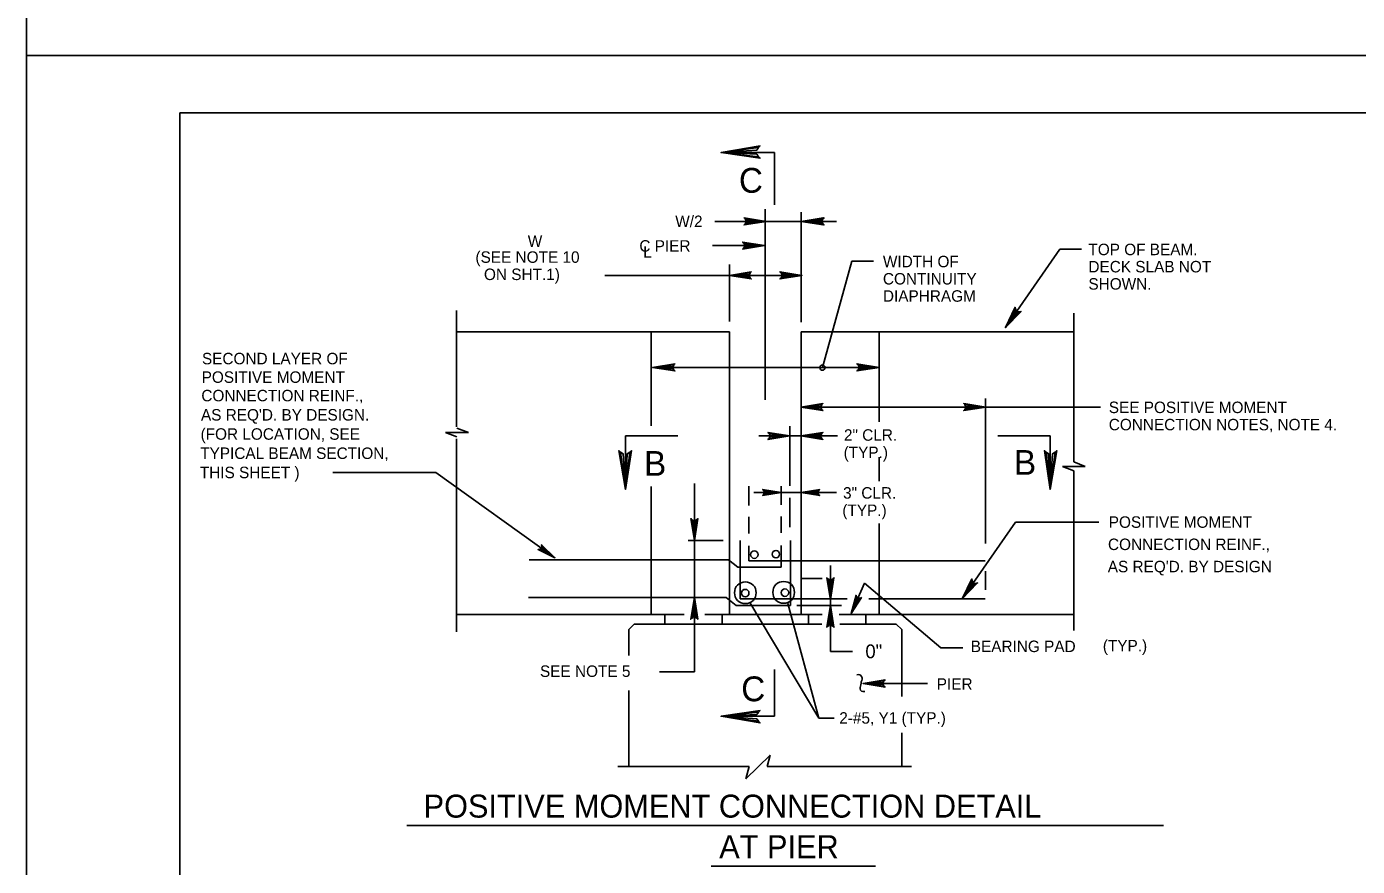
# Model space of a CAD drawing. Extents: x 641517 to 642372, y 298537 to 300319.
# Drawn here: x 641517 to 641864.7, y 299512.8 to 299732.1 of the extents above; entities that cross this region are included whole.
import ezdxf

# ---------------------------------------------------------------- set-up
doc = ezdxf.new("R2010")
doc.units = 0
for name, color, linetype in [('1', 7, 'Continuous'), ('2', 7, 'Continuous'), ('3', 7, 'Continuous'), ('PLT-BNDY', 7, 'Continuous')]:
    doc.layers.add(name, color=color, linetype=linetype)

msp = doc.modelspace()

# ---------------------------------------------------------------- linework, layer by layer
at = {"layer": '1'}
for p, q in [((641709.99, 299634.69), (641709.99, 299684.42)), ((641680.22, 299627.84), (641680.22, 299652.44)), ((641700.62, 299578.61), (641700.62, 299652.44)), ((641719.37, 299578.61), (641719.37, 299652.44)), ((641739.76, 299628.96), (641739.76, 299652.44)), ((641739.76, 299613.39), (641739.76, 299619.71)), ((641680.22, 299578.61), (641680.22, 299612.04)), ((641739.76, 299578.61), (641739.76, 299602.33)), ((641702.81, 299590.97), (641700.38, 299592.86)), ((641702.38, 299580.97), (641699.8, 299583.08))]:
    msp.add_line(p, q, dxfattribs=at)
msp.add_spline([(641733.93, 299562.89), (641734.71, 299562.83), (641735.12, 299562.43), (641735.29, 299561.7), (641735.08, 299561.01), (641734.94, 299560.28), (641734.81, 299559.55), (641734.89, 299558.82), (641735.44, 299558.51), (641736.02, 299558.51)], degree=3, dxfattribs=at)
at = {"layer": '2'}
for p, q in [((641557.05, 299145.62), (641557.05, 299709.62)), ((641557.05, 299709.62), (642343.05, 299709.62)), ((641712.41, 299699.24), (641698.46, 299699.24)), ((641712.41, 299685.61), (641712.41, 299699.24)), ((641719.37, 299654.93), (641719.37, 299683.68)), ((641710.18, 299681.26), (641696.8, 299681.26)), ((641719.42, 299681.26), (641710.18, 299681.26)), ((641728.61, 299681.26), (641719.37, 299681.26)), ((641709.79, 299674.94), (641696.21, 299674.94)), ((641792.61, 299674.03), (641786.93, 299674.03)), ((641700.62, 299655.13), (641700.62, 299670.02)), ((641732.64, 299670.88), (641724.92, 299643.07)), ((641738.22, 299670.88), (641732.64, 299670.88)), ((641700.62, 299667.16), (641668.08, 299667.16)), ((641719.56, 299667.16), (641700.62, 299667.16)), ((641629.36, 299627.61), (641629.36, 299658.02)), ((641790.62, 299618.46), (641790.62, 299657.28)), ((641629.36, 299652.44), (641700.62, 299652.44)), ((641719.37, 299652.44), (641790.62, 299652.44)), ((641739.76, 299643.14), (641680.57, 299643.14)), ((641797.52, 299632.75), (641719.37, 299632.75)), ((641629.41, 299627.29), (641632.43, 299626.11)), ((641716.37, 299612.2), (641716.37, 299627.78)), ((641632.43, 299626.11), (641626.49, 299626.11)), ((641626.49, 299626.11), (641629.41, 299624.97)), ((641629.36, 299574.06), (641629.36, 299624.45)), ((641687.14, 299625.23), (641673.51, 299625.23)), ((641673.51, 299625.23), (641673.51, 299611.28)), ((641728.84, 299625.24), (641708.31, 299625.24)), ((641770.77, 299625.23), (641784.4, 299625.23)), ((641784.4, 299625.23), (641784.4, 299611.28)), ((641793.58, 299617.28), (641787.65, 299617.28)), ((641787.65, 299617.28), (641790.57, 299616.14)), ((641790.57, 299618.46), (641793.58, 299617.28)), ((641790.62, 299574.4), (641790.62, 299616.14)), ((641597.02, 299615.67), (641623.96, 299615.67)), ((641623.96, 299615.67), (641655.06, 299593.42)), ((641691.46, 299597.93), (641691.46, 299612.78)), ((641705.69, 299607.03), (641705.69, 299612.15)), ((641714.15, 299610.46), (641706.96, 299610.46)), ((641714.15, 299607.24), (641714.15, 299612.15)), ((641719.37, 299610.46), (641714.15, 299610.46)), ((641716.37, 299601.42), (641716.37, 299609.05)), ((641728.58, 299610.46), (641719.37, 299610.46)), ((641705.69, 299599.75), (641705.69, 299604.12)), ((641714.15, 299599.95), (641714.15, 299604.22)), ((641797.12, 299602.72), (641775.34, 299602.72)), ((641698.96, 299597.93), (641689.85, 299597.93)), ((641691.46, 299583.08), (641691.46, 299597.93)), ((641703.43, 299582.66), (641703.43, 299597.93)), ((641705.69, 299592.66), (641705.69, 299596.52)), ((641714.15, 299590.97), (641714.15, 299596.62)), ((641716.55, 299580.97), (641716.55, 299597.93)), ((641648.35, 299592.86), (641700.38, 299592.86)), ((641705.69, 299592.66), (641767.44, 299592.66)), ((641702.81, 299590.97), (641714.15, 299590.97)), ((641719.37, 299587.99), (641724.86, 299587.99)), ((641755.88, 299569.86), (641735.94, 299586.82)), ((641648.12, 299583.08), (641699.8, 299583.08)), ((641691.46, 299563.65), (641691.46, 299583.08)), ((641703.43, 299582.66), (641731.4, 299582.66)), ((641737.04, 299582.66), (641767.44, 299582.66)), ((641629.36, 299578.61), (641688.77, 299578.61)), ((641683.74, 299576.08), (641683.74, 299578.61)), ((641694.17, 299578.61), (641719.37, 299578.61)), ((641698.74, 299576.08), (641698.74, 299578.61)), ((641702.38, 299580.97), (641716.55, 299580.97)), ((641729.93, 299580.97), (641718.21, 299580.97)), ((641719.37, 299578.61), (641724.86, 299578.61)), ((641721.24, 299576.08), (641721.24, 299578.61)), ((641729.26, 299578.61), (641790.62, 299578.61)), ((641736.24, 299576.08), (641736.24, 299578.61)), ((641674.36, 299574.67), (641675.77, 299576.08)), ((641674.36, 299567.9), (641674.36, 299574.67)), ((641675.77, 299576.08), (641724.75, 299576.08)), ((641729.48, 299576.08), (641744.21, 299576.08)), ((641745.62, 299574.67), (641744.21, 299576.08)), ((641745.62, 299557.2), (641745.62, 299574.67)), ((641761.62, 299569.86), (641755.88, 299569.86)), ((641712.41, 299564.25), (641712.41, 299552.02)), ((641691.46, 299563.65), (641682.36, 299563.65)), ((641752.34, 299560.59), (641735.55, 299560.59)), ((641674.36, 299538.8), (641674.36, 299558.75)), ((641712.41, 299552.02), (641698.46, 299552.02)), ((641727.99, 299551.57), (641723.96, 299551.57)), ((641745.62, 299538.94), (641745.62, 299547.72)), ((641704.94, 299535.71), (641711.3, 299541.85)), ((641711.3, 299541.85), (641710.47, 299538.93)), ((641705.8, 299538.93), (641671.44, 299538.93)), ((641704.91, 299535.71), (641705.77, 299538.93)), ((641748.16, 299538.93), (641710.47, 299538.93)), ((641616.38, 299523.5), (641814.01, 299523.5)), ((641695.83, 299512.92), (641738.77, 299512.92))]:
    msp.add_line(p, q, dxfattribs=at)
for points in [[(641708.18, 299700.53), (641707.75, 299699.89), (641698.46, 299699.24), (641708.18, 299700.53), (641708.62, 299700.97), (641698.46, 299699.24), (641707.75, 299698.81), (641708.18, 299698.16), (641698.46, 299699.24), (641708.62, 299697.73), (641708.18, 299698.16)], [(641776.43, 299657.67), (641775.99, 299657.73), (641772.71, 299653.52), (641776.43, 299657.67), (641776.8, 299657.77), (641772.71, 299653.52), (641775.53, 299658.05), (641775.31, 299658.43), (641772.71, 299653.52), (641775.26, 299658.83), (641775.31, 299658.43)], [(641686.11, 299642.44), (641685.9, 299642.84), (641680.57, 299643.14), (641686.11, 299642.44), (641686.39, 299642.2), (641680.57, 299643.14), (641685.9, 299643.4), (641686.09, 299643.8), (641680.57, 299643.14), (641686.39, 299644.06), (641686.09, 299643.8)], [(641734.23, 299643.83), (641734.43, 299643.43), (641739.76, 299643.14), (641734.23, 299643.83), (641733.94, 299644.07), (641739.76, 299643.14), (641734.44, 299642.87), (641734.24, 299642.48), (641739.76, 299643.14), (641733.94, 299642.21), (641734.24, 299642.48)], [(641672.21, 299621), (641672.86, 299620.57), (641673.51, 299611.28), (641672.21, 299621), (641671.78, 299621.43), (641673.51, 299611.28), (641673.94, 299620.57), (641674.59, 299621), (641673.51, 299611.28), (641675.02, 299621.43), (641674.59, 299621)], [(641785.7, 299621), (641785.05, 299620.57), (641784.4, 299611.28), (641785.7, 299621), (641786.13, 299621.43), (641784.4, 299611.28), (641783.97, 299620.57), (641783.32, 299621), (641784.4, 299611.28), (641782.89, 299621.43), (641783.32, 299621)], [(641709.53, 299611.04), (641709.7, 299610.71), (641714.15, 299610.46), (641709.53, 299611.04), (641709.3, 299611.24), (641714.15, 299610.46), (641709.71, 299610.24), (641709.55, 299609.91), (641714.15, 299610.46), (641709.3, 299609.69), (641709.55, 299609.91)], [(641723.98, 299609.88), (641723.81, 299610.22), (641719.37, 299610.46), (641723.98, 299609.88), (641724.22, 299609.68), (641719.37, 299610.46), (641723.8, 299610.68), (641723.97, 299611.01), (641719.37, 299610.46), (641724.22, 299611.23), (641723.97, 299611.01)], [(641651.6, 299596.52), (641651.55, 299596.14), (641655.06, 299593.42), (641651.6, 299596.52), (641651.52, 299596.82), (641655.06, 299593.42), (641651.29, 299595.76), (641650.97, 299595.58), (641655.06, 299593.42), (641650.64, 299595.54), (641650.97, 299595.58)], [(641734.84, 299582.88), (641734.47, 299582.85), (641732.46, 299578.89), (641734.84, 299582.88), (641735.12, 299583.01), (641732.46, 299578.89), (641734.04, 299583.04), (641733.8, 299583.32), (641732.46, 299578.89), (641733.7, 299583.64), (641733.8, 299583.32)], [(641708.18, 299550.72), (641707.75, 299551.37), (641698.46, 299552.02), (641708.18, 299550.72), (641708.62, 299550.29), (641698.46, 299552.02), (641707.75, 299552.45), (641708.18, 299553.1), (641698.46, 299552.02), (641708.62, 299553.53), (641708.18, 299553.1)]]:
    msp.add_lwpolyline(points, dxfattribs=at)
for centre, radius in [((641724.92, 299643.07), 0.679), ((641707.13, 299594.24), 0.977), ((641712.76, 299594.35), 0.977), ((641704.78, 299584.3), 2.84), ((641704.76, 299584.19), 0.977), ((641714.79, 299584.39), 2.84), ((641715.13, 299584.31), 0.977)]:
    msp.add_circle(centre, radius, dxfattribs=at)
at = {"layer": '3'}
for p, q in [((641772.71, 299653.52), (641786.93, 299674.03)), ((641642.2, 299652.44), (641642.2, 299652.44)), ((641767.5, 299597.14), (641767.5, 299635)), ((641761.43, 299582.66), (641775.34, 299602.72)), ((641727.01, 299591.38), (641727.01, 299582.66)), ((641767.5, 299585.05), (641767.5, 299589.95)), ((641735.94, 299586.82), (641732.46, 299578.89)), ((641723.96, 299551.57), (641705.94, 299581.71)), ((641723.96, 299551.57), (641715.84, 299581.46)), ((641727.01, 299582.66), (641727.01, 299580.98)), ((641727.01, 299582.49), (641727.01, 299582.49)), ((641727.01, 299580.98), (641727.01, 299580.98)), ((641727.01, 299580.98), (641727.01, 299568.97)), ((641727.01, 299568.97), (641732.78, 299568.97))]:
    msp.add_line(p, q, dxfattribs=at)
for points in [[(641704.73, 299681.95), (641704.94, 299681.55), (641710.18, 299681.26), (641704.73, 299681.95), (641704.46, 299682.19), (641710.18, 299681.26), (641704.94, 299681), (641704.75, 299680.61), (641710.18, 299681.26), (641704.46, 299680.35), (641704.75, 299680.61)], [(641704.73, 299681.95), (641704.94, 299681.55), (641710.18, 299681.26), (641704.73, 299681.95), (641704.46, 299682.19), (641710.18, 299681.26), (641704.94, 299681), (641704.75, 299680.61), (641710.18, 299681.26), (641704.46, 299680.35), (641704.75, 299680.61)], [(641724.82, 299680.58), (641724.61, 299680.97), (641719.37, 299681.26), (641724.82, 299680.58), (641725.09, 299680.34), (641719.37, 299681.26), (641724.61, 299681.52), (641724.8, 299681.91), (641719.37, 299681.26), (641725.09, 299682.17), (641724.8, 299681.91)], [(641725.08, 299680.58), (641724.87, 299680.97), (641719.63, 299681.26), (641725.08, 299680.58), (641725.35, 299680.34), (641719.63, 299681.26), (641724.87, 299681.52), (641725.06, 299681.91), (641719.63, 299681.26), (641725.35, 299682.17), (641725.06, 299681.91)], [(641704.34, 299674.26), (641704.55, 299674.65), (641709.79, 299674.94), (641704.34, 299674.26), (641704.06, 299674.02), (641709.79, 299674.94), (641704.55, 299675.2), (641704.36, 299675.59), (641709.79, 299674.94), (641704.06, 299675.85), (641704.36, 299675.59)], [(641706.07, 299666.48), (641705.86, 299666.87), (641700.62, 299667.16), (641706.07, 299666.48), (641706.34, 299666.24), (641700.62, 299667.16), (641705.86, 299667.42), (641706.05, 299667.81), (641700.62, 299667.16), (641706.34, 299668.07), (641706.05, 299667.81)], [(641714.11, 299667.85), (641714.31, 299667.45), (641719.56, 299667.16), (641714.11, 299667.85), (641713.83, 299668.09), (641719.56, 299667.16), (641714.31, 299666.9), (641714.12, 299666.51), (641719.56, 299667.16), (641713.83, 299666.25), (641714.12, 299666.51)], [(641724.77, 299632.08), (641724.56, 299632.48), (641719.32, 299632.77), (641724.77, 299632.08), (641725.04, 299631.85), (641719.32, 299632.77), (641724.56, 299633.03), (641724.75, 299633.42), (641719.32, 299632.77), (641725.04, 299633.68), (641724.75, 299633.42)], [(641762.12, 299633.43), (641762.32, 299633.04), (641767.57, 299632.75), (641762.12, 299633.43), (641761.84, 299633.67), (641767.57, 299632.75), (641762.32, 299632.49), (641762.13, 299632.1), (641767.57, 299632.75), (641761.84, 299631.84), (641762.13, 299632.1)], [(641710.97, 299625.93), (641711.17, 299625.53), (641716.42, 299625.24), (641710.97, 299625.93), (641710.69, 299626.17), (641716.42, 299625.24), (641711.18, 299624.98), (641710.99, 299624.59), (641716.42, 299625.24), (641710.69, 299624.33), (641710.99, 299624.59)], [(641724.76, 299624.55), (641724.56, 299624.95), (641719.31, 299625.24), (641724.76, 299624.55), (641725.04, 299624.31), (641719.31, 299625.24), (641724.55, 299625.5), (641724.74, 299625.89), (641719.31, 299625.24), (641725.04, 299626.15), (641724.74, 299625.89)], [(641692.15, 299603.38), (641691.75, 299603.18), (641691.46, 299597.93), (641692.15, 299603.38), (641692.39, 299603.66), (641691.46, 299597.93), (641691.2, 299603.17), (641690.81, 299603.36), (641691.46, 299597.93), (641690.55, 299603.66), (641690.81, 299603.36)], [(641727.69, 299587.94), (641727.3, 299587.73), (641727.01, 299582.49), (641727.69, 299587.94), (641727.93, 299588.21), (641727.01, 299582.49), (641726.75, 299587.73), (641726.36, 299587.92), (641727.01, 299582.49), (641726.1, 299588.21), (641726.36, 299587.92)], [(641727.69, 299587.94), (641727.3, 299587.73), (641727.01, 299582.49), (641727.69, 299587.94), (641727.93, 299588.21), (641727.01, 299582.49), (641726.75, 299587.73), (641726.36, 299587.92), (641727.01, 299582.49), (641726.1, 299588.21), (641726.36, 299587.92)], [(641765.1, 299586.74), (641764.66, 299586.8), (641761.43, 299582.66), (641765.1, 299586.74), (641765.45, 299586.84), (641761.43, 299582.66), (641764.2, 299587.11), (641763.99, 299587.49), (641761.43, 299582.66), (641763.95, 299587.88), (641763.99, 299587.49)], [(641690.78, 299577.63), (641691.17, 299577.84), (641691.46, 299583.08), (641690.78, 299577.63), (641690.54, 299577.35), (641691.46, 299583.08), (641691.72, 299577.84), (641692.11, 299577.65), (641691.46, 299583.08), (641692.37, 299577.35), (641692.11, 299577.65)], [(641726.32, 299575.53), (641726.72, 299575.74), (641727.01, 299580.98), (641726.32, 299575.53), (641726.09, 299575.26), (641727.01, 299580.98), (641727.27, 299575.74), (641727.66, 299575.55), (641727.01, 299580.98), (641727.92, 299575.26), (641727.66, 299575.55)], [(641741, 299559.91), (641740.79, 299560.3), (641735.55, 299560.59), (641741, 299559.91), (641741.28, 299559.67), (641735.55, 299560.59), (641740.79, 299560.85), (641740.98, 299561.24), (641735.55, 299560.59), (641741.28, 299561.5), (641740.98, 299561.24)], [(641739.18, 299560.14), (641739.05, 299560.4), (641735.55, 299560.59), (641739.18, 299560.14), (641739.37, 299559.98), (641735.55, 299560.59), (641739.04, 299560.77), (641739.17, 299561.03), (641735.55, 299560.59), (641739.37, 299561.2), (641739.17, 299561.03)]]:
    msp.add_lwpolyline(points, dxfattribs=at)
at = {"layer": 'PLT-BNDY'}
for points in [[(641517.05, 300318.62), (642358.05, 300318.62), (642358.05, 299724.62), (641517.05, 299724.62)], [(641517.05, 299724.62), (642358.05, 299724.62), (642358.05, 299130.62), (641517.05, 299130.62)]]:
    msp.add_lwpolyline(points, close=True, dxfattribs=at)

# ---------------------------------------------------------------- texts
at = {"layer": '2'}
for s, height, p in [('C', 6.48, (641703.11, 299688.74)), ('(SEE NOTE 10', 3, (641634.28, 299670.44)), ('  ON SHT.1)', 3, (641634.28, 299665.94)), ('B', 6.48, (641678.34, 299614.82)), ('B', 6.48, (641774.96, 299615.08)), ('SEE NOTE 5', 3, (641651.14, 299562.3)), ('C', 6.48, (641703.71, 299555.95)), ('POSITIVE MOMENT CONNECTION DETAIL', 6, (641620.74, 299525.56)), ('AT PIER', 6, (641697.96, 299514.97))]:
    msp.add_text(s, height=height, dxfattribs=at).set_placement(p)
at = {"layer": '3'}
for s, height, p in [('W/2', 2.997, (641686.48, 299679.78)), ('W', 3, (641647.95, 299674.6)), ('C PIER', 2.997, (641677.1, 299673.36)), ('TOP OF BEAM.', 2.9969, (641794.4, 299672.44)), ('L', 3, (641678.11, 299671.79)), ('WIDTH OF', 2.997, (641740.72, 299669.28)), ('DECK SLAB NOT', 2.9969, (641794.4, 299667.94)), ('CONTINUITY', 2.997, (641740.72, 299664.78)), ('SHOWN.', 2.997, (641794.4, 299663.44)), ('DIAPHRAGM', 2.997, (641740.72, 299660.28)), ('SECOND LAYER OF', 2.9968, (641562.85, 299643.94)), ('POSITIVE MOMENT', 2.9968, (641562.77, 299639.1)), ('CONNECTION REINF.,', 2.9968, (641562.69, 299634.27)), ('SEE POSITIVE MOMENT', 2.9957, (641799.72, 299631.2)), ("AS REQ'D. BY DESIGN.", 2.9968, (641562.59, 299629.25)), ('CONNECTION NOTES, NOTE 4.', 2.9957, (641799.72, 299626.7)), ('(FOR LOCATION, SEE', 2.9968, (641562.49, 299624.24)), ('2" CLR.', 2.997, (641730.54, 299623.98)), ('TYPICAL BEAM SECTION,', 2.9968, (641562.39, 299619.22)), ('(TYP.)', 2.997, (641730.46, 299619.45)), ('THIS SHEET )', 2.9968, (641562.29, 299614.2)), ('3" CLR.', 2.997, (641730.31, 299608.86)), ('(TYP.)', 2.997, (641730.12, 299604.33)), ('POSITIVE MOMENT', 2.9968, (641799.71, 299601.24)), ('CONNECTION REINF.,', 2.9968, (641799.51, 299595.43)), ("AS REQ'D. BY DESIGN", 2.9968, (641799.45, 299589.63)), ('0"', 3.595, (641736.14, 299567.18)), ('BEARING PAD', 2.9968, (641763.67, 299568.79)), ('(TYP.)', 2.997, (641798.16, 299568.97)), ('PIER', 2.997, (641754.78, 299558.95)), ('2-#5, Y1 (TYP.)', 2.9968, (641729.32, 299550.1))]:
    msp.add_text(s, height=height, dxfattribs=at).set_placement(p)

doc.saveas('drawing.dxf')
